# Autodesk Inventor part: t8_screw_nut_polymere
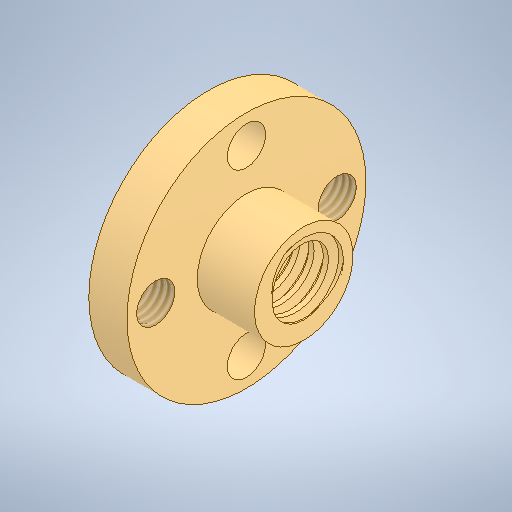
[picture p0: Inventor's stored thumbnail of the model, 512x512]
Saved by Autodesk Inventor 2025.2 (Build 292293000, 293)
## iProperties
Created: 2021-12
Part Number: t8_screw_nut_polymere
Material: Nylon 6
Document SubType Name: Modeling
Designer: BennF
Density: 1.12 g/cm^3
Appearance: Smooth - Black
Sending System: Autodesk Translation Framework v10.10.0.1391
Preprocessor: ST-DEVELOPER v18.1
Title: C:/Users/danig/Dropbox/Fusion/Perfil/T8 Screw nut v0.step
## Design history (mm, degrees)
feature "Body1"
sketch "Sketch1"
  geometry: C1 r 11 at (0, 0) reference; 1 further point
extrude "Extrusion1" cut sketch "Sketch1" stored distance "d0" = 10; taper "d1" = 0 deg
sketch "Sketch2"
  geometry: C1 r 12.5 at (0, 0); C2 r 5 at (0, 0); 1 further point
  constraints: 2 centre point, 2 coincident
  dimensions: "d2" = 25 diameter of C1; "d5" = 10 diameter of C2
extrude "Extrusion2" join sketch "Sketch2" stored distance "d3" = 10; taper "d4" = 0 deg
sketch "Sketch3"
  geometry: A1 r 9.5 centre (0, 0) between (0, 9.5) and (-9.5, 0); 3 further points
  constraints: 4 point on circle, 2 horizontal alignment, 2 vertical alignment, 1 centre point, 1 coincident
  dimensions: "d13" = 19 diameter of A1
hole "Hole1" sketch "Sketch3" at (-9.5, 0), (9.5, 0), (0, -9.5), (0, 9.5) diameter "d6" = 4; stored, may be unused: countersink angle "d10" = 89.9544 deg, drill point angle "d12" = 118 deg; dims "d7" = 6, "d8" = 12.5, "d9" = 2, "d11" = 8
sketch "Sketch4"
  geometry: C1 r 2 at (0, 9.5) reference; C2 r 2 at (0, -9.5) reference; C3 r 2 at (-9.5, 0) reference; C4 r 2 at (9.5, 0) reference; C5 r 12.5 at (0, 0) reference; C6 r 5.15 at (0, 0) reference; 1 further point
extrude "Extrusion3" join sketch "Sketch4" distance "d14" = 0.5; taper "d15" = 0 deg
sketch "Sketch5"
  geometry: C1 r 12.5 at (0, 0) reference; 1 further point
extrude "Extrusion4" cut sketch "Sketch5" distance "d16" = 3.5; taper "d17" = 0 deg
thread "Thread1" dims "d18" = 4, "d19" = 0
thread "Thread2" dims "d20" = 4, "d21" = 0
body "Solid1"
node "Projected Loop1"
